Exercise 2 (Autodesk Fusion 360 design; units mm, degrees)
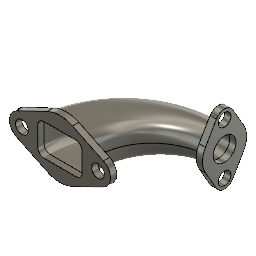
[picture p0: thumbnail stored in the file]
sketch "Sketch1" plane through (0, 0, 0) normal (0, 1, 0) x axis (1, 0, 0)
  arc A1 centre (0, 0) radius 120 clockwise from (-120, 0) to (0, 120)
  point P1 (0, 0)
  point P2 (0, 0)
  point P4 (-120, 0)
  point P3 (0, 120)
  coincident P1 P2
  horizontal P1 P4
  vertical P1 P3
  dimension "d1" radius A1 = 120
sketch "Sketch2" plane through (0, 0, 0) normal (0, 0, 1) x axis (1, 0, 0)
  line L1 (-145, 30) -> (-95, 30)
  line L2 (-160, -15) -> (-160, 15)
  line L3 (-95, -30) -> (-145, -30)
  line L4 (-80, 15) -> (-80, -15)
  line L5 (-160, -30) -> (-80, 30)
  line L6 (-80, -30) -> (-160, 30)
  arc A1 centre (-145, 15) radius 15 clockwise from (-160, 15) to (-145, 30)
  arc A2 centre (-95, 15) radius 15 clockwise from (-95, 30) to (-80, 15)
  arc A3 centre (-95, -15) radius 15 clockwise from (-80, -15) to (-95, -30)
  arc A4 centre (-145, -15) radius 15 clockwise from (-145, -30) to (-160, -15)
  point P6 (-120, 0)
  point P7 (-120, 0)
  point P3 (-160, 30)
  point P5 (-80, -30)
  point P4 (-160, -30)
  perpendicular L1 L2
  parallel L1 L3
  parallel L2 L4
  horizontal L1
  coincident L5 P6
  coincident L6 P6
  coincident P6 P7
  coincident P3 L1
  coincident P3 L2
  tangent L1 A1
  tangent L2 A1
  tangent L4 A2
  tangent L1 A2
  equal A1 A2
  coincident P5 L4
  coincident P5 L3
  tangent L4 A3
  tangent L3 A3
  equal A1 A3
  coincident P4 L3
  coincident P4 L2
  tangent L3 A4
  tangent L2 A4
  equal A1 A4
  dimension "d2" distance P4 P5 = 80
  dimension "d3" distance P3 P4 = 60
  dimension "d5" radius A1 = 15
sketch "Sketch3" plane through (0, 0, 0) normal (1, 0, 0) x axis (0, 0, -1)
  circle C1 centre (120, 0) radius 23
  point P2 (120, 0)
  point P3 (120, 0)
  coincident P2 P3
  dimension "d4" diameter C1 = 46
loft "Loft1" sketch "Sketch2" + "Sketch3"
sketch "Sketch5" plane through (0, 0, 0) normal (0, 0, 1) x axis (1, 0, 0)
  dimension "d6" distance = 5
sketch "Sketch6" plane through (0, 0, 0) normal (1, 0, 0) x axis (0, 0, -1)
  circle C1 centre (120, 0) radius 23
  circle C2 centre (120, 0) radius 18
  dimension "d7" = 5
loft "Loft2" sketch "Sketch5" + "Sketch6"
sketch "Sketch7" plane through (0, 0, 0) normal (0, 0, 1) x axis (1, 0, 0)
  line L1 (-120, 0) -> (0, 0)
  line L2 (-120, 73.4908) -> (-120, 0)
  line L3 (-139.9333, 41.4568) -> (-188.6667, 18.0247)
  line L4 (-51.3333, 18.0247) -> (-100.0667, 41.4568)
  line L5 (-139.9333, -41.4568) -> (-188.6667, -18.0247)
  line L6 (-51.3333, -18.0247) -> (-100.0667, -41.4568)
  arc A1 centre (-180, 0) radius 20 clockwise from (-188.6667, -18.0247) to (-188.6667, 18.0247)
  arc A2 centre (-120, 0) radius 46 clockwise from (-100.0667, -41.4568) to (-139.9333, -41.4568)
  arc A3 centre (-120, 0) radius 46 clockwise from (-139.9333, 41.4568) to (-100.0667, 41.4568)
  arc A4 centre (-60, 0) radius 20 clockwise from (-51.3333, 18.0247) to (-51.3333, -18.0247)
  point P2 (-120, 0)
  point P3 (-120, 0)
  point P5 (-60, 0)
  point P7 (-120, 0)
  point P8 (-120, 0)
  point P4 (-180, 0)
  point P12 (-100.0667, 41.4568)
  point P18 (-120, 0)
  coincident P2 P3
  coincident P5 L1
  equal A1 A4
  coincident P7 P8
  perpendicular L1 L2
  symmetric P4 P5 L2
  coincident P12 A2
  tangent L4 A4
  tangent L5 A2
  tangent L6 A4
  tangent L6 A2
  tangent L4 A2
  tangent L3 A1
  tangent L5 A1
  tangent L3 A3
  coincident P2 P18
  dimension "d10" radius A3 = 46
  dimension "d11" radius A1 = 20
  dimension "d12" distance P4 P5 = 120
extrude "Extrude1" add sketch "Sketch7" profile of A3 A1 A4 L1 L3 L4 L5 L6 along normal blind 10
sketch "Sketch8" plane through (0, 0, 0) normal (1, 0, 0) x axis (0, 0, -1)
  line L1 (89.6891, 17.5) -> (107.0096, 47.5)
  line L2 (150.3109, 17.5) -> (132.9904, 47.5)
  line L3 (132.9904, -47.5) -> (150.3109, -17.5)
  line L4 (89.6891, -17.5) -> (107.0096, -47.5)
  line L5 (170.6155, 0) -> (120, 0)
  circle C1 centre (120, 0) radius 23
  arc A1 centre (120, -40) radius 15 clockwise from (132.9904, -47.5) to (107.0096, -47.5)
  arc A2 centre (120, 0) radius 35 clockwise from (150.3109, 17.5) to (150.3109, -17.5)
  arc A3 centre (120, 0) radius 35 clockwise from (89.6891, -17.5) to (89.6891, 17.5)
  arc A4 centre (120, 40) radius 15 clockwise from (107.0096, 47.5) to (132.9904, 47.5)
  point P3 (120, 0)
  point P4 (120, 40)
  point P5 (120, -40)
  point P7 (89.6891, 17.5)
  point P14 (120, 0)
  point P15 (120, 0)
  concentric C1 A2
  equal A1 A4
  vertical P3 P4
  vertical P3 P5
  coincident P7 A2
  tangent L1 A2
  tangent L2 A2
  tangent L3 A1
  tangent L4 A2
  tangent L4 A1
  tangent L2 A4
  tangent L1 A4
  tangent L3 A2
  concentric A2 A3
  coincident P14 P15
  horizontal L5
  symmetric P4 P5 L5
  dimension "d15" radius A2 = 35
  dimension "d16" distance P4 P5 = 80
  dimension "d17" radius A1 = 15
extrude "Extrude2" add sketch "Sketch8" profile of C1 A3 A4 A1 L1 L2 L3 L4 along normal blind 10
sketch "Sketch9" plane through (0, 0, 0) normal (0, 0, -1) x axis (-1, 0, 0)
  line L1 (139.9333, 41.4568) -> (188.6667, 18.0247)
  line L2 (51.3333, 18.0247) -> (100.0667, 41.4568)
  line L3 (100.0667, -41.4568) -> (51.3333, -18.0247)
  line L4 (188.6667, -18.0247) -> (139.9333, -41.4568)
  arc A1 centre (180, 0) radius 20 clockwise from (188.6667, 18.0247) to (188.6667, -18.0247)
  arc A2 centre (120, 0) radius 46 clockwise from (100.0667, 41.4568) to (139.9333, 41.4568)
  arc A3 centre (60, 0) radius 20 clockwise from (51.3333, -18.0247) to (51.3333, 18.0247)
  arc A4 centre (120, 0) radius 46 clockwise from (139.9333, -41.4568) to (100.0667, -41.4568)
  circle C1 centre (180, 0) radius 10
  circle C2 centre (60, 0) radius 10
  concentric A1 C1
  concentric A3 C2
  equal C1 C2
  dimension "d20" diameter C1 = 20
extrude "Extrude3" cut sketch "Sketch9" profile of C1 C2 no distance stored
sketch "Sketch10" plane through (10, 0, 0) normal (1, 0, 0) x axis (0, 0, -1)
  line L1 (132.9904, 47.5) -> (150.3109, 17.5)
  line L2 (89.6891, 17.5) -> (107.0096, 47.5)
  line L3 (107.0096, -47.5) -> (89.6891, -17.5)
  line L4 (150.3109, -17.5) -> (132.9904, -47.5)
  arc A1 centre (120, 0) radius 35 clockwise from (150.3109, 17.5) to (150.3109, -17.5)
  arc A2 centre (120, 40) radius 15 clockwise from (107.0096, 47.5) to (132.9904, 47.5)
  arc A3 centre (120, 0) radius 35 clockwise from (89.6891, -17.5) to (89.6891, 17.5)
  arc A4 centre (120, -40) radius 15 clockwise from (132.9904, -47.5) to (107.0096, -47.5)
  circle C1 centre (120, 40) radius 10
  circle C2 centre (120, -40) radius 10
  concentric A2 C1
  concentric A4 C2
  equal C1 C2
  dimension "d22" diameter C1 = 20
extrude "Extrude4" cut sketch "Sketch10" profile of C1 C2 to an object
